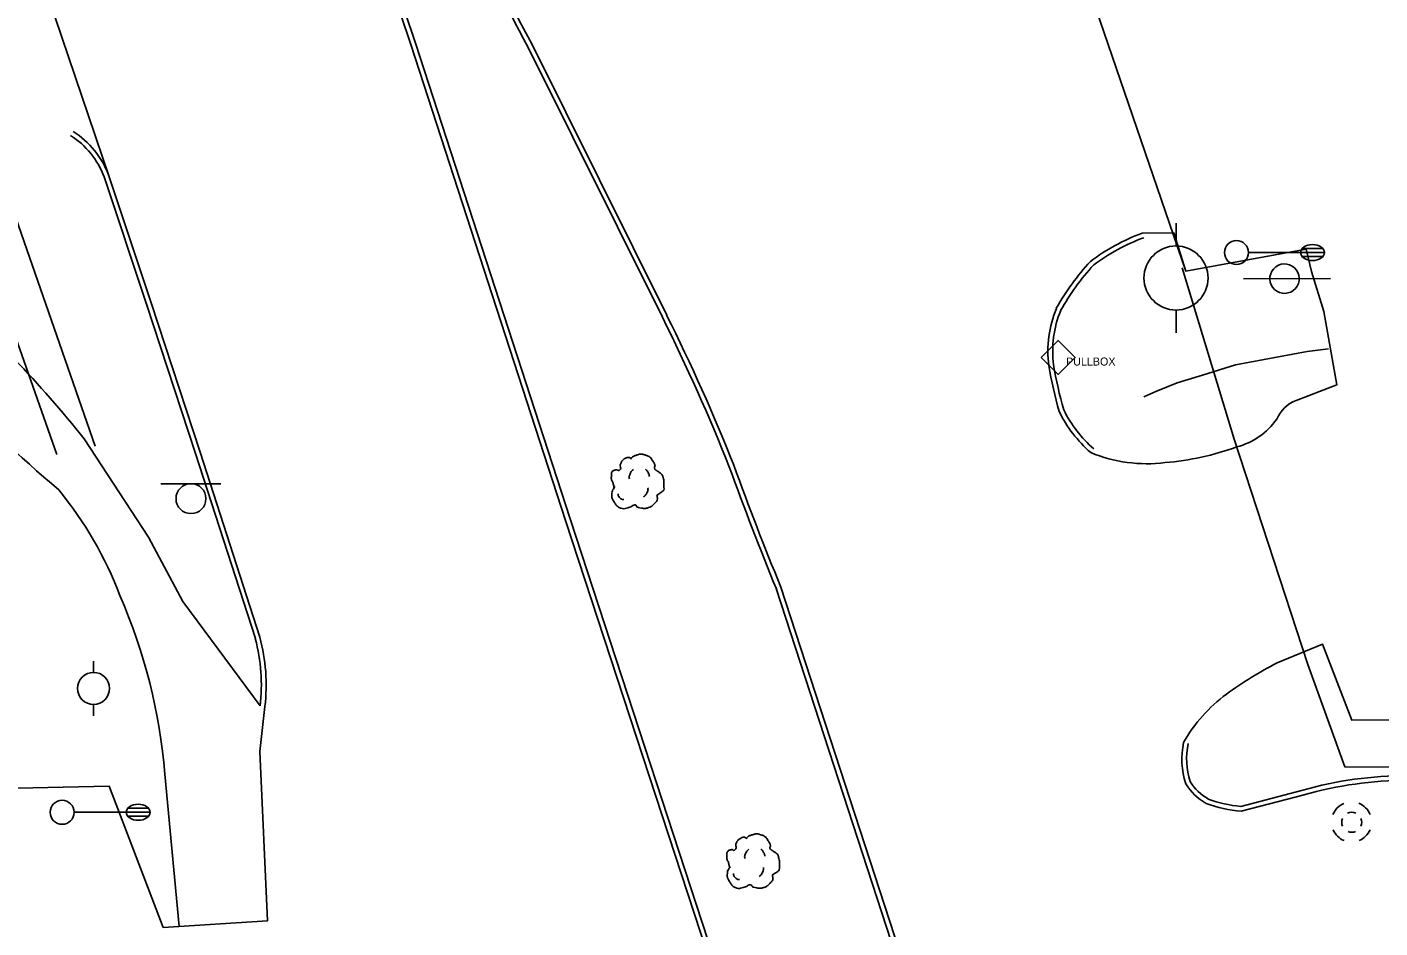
# Model space of a CAD drawing. Extents: x 2145380 to 2157287, y 139568 to 149130.
# Drawn here: x 2147392.4 to 2147561.3, y 142646.5 to 142759 of the extents above; entities that cross this region are included whole.
import ezdxf

# ---------------------------------------------------------------- set-up
doc = ezdxf.new("R2010")
doc.units = 0
for name, color, linetype in [('Default', 7, 'Continuous'), ('TOPO_Asphalt', 7, 'Continuous'), ('TOPO_Concrete', 7, 'Continuous'), ('TOPO_Curb Back', 7, 'Continuous'), ('TOPO_Dirt Grav', 7, 'Continuous'), ('TOPO_DRAIN_Manhole', 7, 'Continuous'), ('TOPO_Fence', 7, 'Continuous'), ('TOPO_Flowline', 7, 'Continuous'), ('TOPO_Guardrail', 7, 'Continuous'), ('TOPO_Light Pole', 7, 'Continuous'), ('TOPO_Power Pole', 7, 'Continuous'), ('TOPO_Power Pullbox', 7, 'Continuous'), ('TOPO_Sign', 7, 'Continuous'), ('TOPO_Tree', 7, 'Continuous')]:
    doc.layers.add(name, color=color, linetype=linetype)

# ---------------------------------------------------------------- blocks, each defined once
blk = doc.blocks.new('POWPOL')
at = {"layer": 'TOPO_Power Pole'}
for p, q in [((0, 10.16), (0, 17.34)), ((0, -10.16), (0, -17.34))]:
    blk.add_line(p, q, dxfattribs=at)
blk.add_circle((0, 0), 10.16, dxfattribs=at)
blk = doc.blocks.new('LP')
at = {"layer": 'TOPO_Light Pole'}
blk.add_line((3.81, 0), (20.32, 0), dxfattribs=at)
for points in [[(20.32, 0), (27.94, 0)], [(20.32, 0), (23.5, 0)], [(20.83, 1.27), (27.43, 1.27)], [(20.83, 1.27), (23.5, 1.27)], [(23.71, 1.27), (27.43, 1.27)], [(23.71, 0), (27.94, 0)], [(20.83, -1.27), (27.43, -1.27)], [(20.83, -1.27), (23.5, -1.27)], [(23.71, -1.27), (27.43, -1.27)]]:
    blk.add_lwpolyline(points, dxfattribs=at)
blk.add_circle((0, 0), 3.81, dxfattribs=at)
blk.add_ellipse((24.13, 0), major_axis=(3.81, 0), ratio=0.666667, dxfattribs=at)
blk = doc.blocks.new('MHEXST')
at = {"layer": 'TOPO_DRAIN_Manhole'}
for centre, radius, start, end in [((-0.14, 0.26), 12.7, 112.97475, 158.26364), ((-0.14, 0.26), 12.7, 22.07441, 68.69913), ((-0.08, 0.11), 6.35, 157.97219, 204.16105), ((-0.08, 0.11), 6.35, 66.19406, 113.69103), ((-0.08, 0.11), 6.35, 336.80229, 21.40458), ((-0.14, 0.26), 12.7, 202.6921, 248.19382), ((-0.08, 0.11), 6.35, 248.57914, 293.19947), ((-0.14, 0.26), 12.7, 291.79631, 337.30323)]:
    blk.add_arc(centre, radius, start, end, dxfattribs=at)
blk = doc.blocks.new('TREE')
at = {"layer": 'TOPO_Tree'}
for points in [[(-14.07, -0.4), (-14.17, 0.5), (-14.37, 1.38), (-14.6, 2.25), (-14.84, 3.17), (-15.47, 3.96), (-15.66, 4.9), (-15.8, 5.59), (-15.71, 6.31), (-15.66, 7.01), (-15.6, 7.91), (-15.72, 8.8), (-15.13, 9.66), (-14.62, 10.42), (-13.76, 10.49), (-13.02, 10.72), (-12.18, 10.98), (-11.06, 10), (-10.37, 10.72), (-9.4, 11.74), (-10.29, 13.28), (-9.84, 14.42), (-9.56, 15.15), (-9.32, 15.89), (-8.78, 16.54), (-8.18, 17.26), (-7.5, 17.68), (-6.67, 18.13), (-6.14, 18.41), (-5.61, 18.61), (-5.08, 18.66), (-4.55, 18.71), (-4.02, 18.54), (-3.49, 18.13)], [(-3.49, 17.6), (-3.07, 18.27), (-2.58, 18.8), (-1.9, 19.19), (-1.05, 19.68), (-0.19, 19.96), (0.74, 20.24), (1.62, 20.51), (2.51, 20.82), (3.39, 20.77), (4.1, 20.73), (4.8, 20.47), (5.51, 20.24), (6.43, 19.95), (7.32, 19.73), (8.15, 19.19), (9.36, 18.4), (10.02, 17.21), (10.8, 16.01), (11.24, 15.33), (11.58, 14.62), (11.86, 13.89), (12.17, 13.08), (11.37, 12.02), (11.86, 11.25), (12, 11.03), (12.18, 10.86), (12.39, 10.72), (12.91, 10.35), (13.45, 10.02), (13.97, 9.66), (14.7, 9.16), (15.41, 8.68), (16.09, 8.07), (16.7, 7.53), (16.93, 6.73), (17.15, 5.95), (17.59, 4.38), (17.71, 2.77), (17.68, 1.19), (17.65, -0.25), (17.83, -2.22), (16.62, -3.04), (15.47, -3.83), (14.31, -4.58), (13.16, -5.35)], [(-4.21, 5.09), (-4.46, 6.09), (-4.3, 7.21), (-3.84, 8.21), (-3.33, 9.34), (-2.71, 10.27), (-1.64, 10.97)], [(5.89, 11.15), (6.5, 10.68), (6.96, 10.17), (7.36, 9.5), (7.93, 8.56), (8.31, 7.6), (8.46, 6.56)], [(13.16, -5.34), (13.25, -5.81), (13.36, -6.28), (13.45, -6.75), (13.76, -8.52), (12.24, -10.03), (10.8, -11.51), (9.98, -12.34), (9.13, -12.77), (8.15, -13.1), (5.97, -13.83), (3.32, -13.56), (1.27, -13.1), (0.49, -12.92), (-0.06, -11.44), (-0.84, -11.51), (-2.04, -11.61), (-3.28, -12.78), (-4.55, -13.1), (-6.06, -13.47), (-7.77, -14.03), (-9.31, -13.62), (-11.36, -13.09), (-12.84, -11.41), (-14.07, -9.39), (-15.32, -7.35), (-15.61, -5.13), (-15.13, -3.04), (-14.87, -1.89), (-13.91, -0.75), (-13.54, 0.13)], [(-11.38, -4.46), (-11.47, -5.41), (-11.03, -6.32), (-10.09, -7.22), (-9.3, -7.97), (-8.49, -8.26), (-7.7, -8.14)], [(4.79, -6.29), (5.71, -5.66), (6.3, -4.92), (6.81, -3.91), (7.36, -2.81), (7.63, -1.7), (7.54, -0.6)]]:
    blk.add_open_spline(points, degree=3, dxfattribs=at)
blk = doc.blocks.new('pulbox')
at = {"layer": 'Default'}
blk.add_lwpolyline([(-5.38, -0.01), (-0.02, 5.42), (5.4, 0.06), (0.05, -5.36), (-5.38, -0.01)], dxfattribs=at)
blk.add_text('PULLBOX', height=2.54, dxfattribs=at).set_placement((2.54, -2.54))

msp = doc.modelspace()

# ---------------------------------------------------------------- linework, layer by layer
at = {"layer": 'TOPO_Asphalt'}
msp.add_line((2147379.12, 142809.78), (2147402.56, 142740.4), dxfattribs=at)
for points in [[(2147550.86, 142712.35), (2147555.96, 142714.29), (2147554.33, 142723.44), (2147552.81, 142728.43), (2147552.15, 142731.25), (2147537.08, 142728.5), (2147535.58, 142733.28), (2147531.64, 142733.22)], [(2147422.07, 142674.13), (2147421.42, 142668.5), (2147422.4, 142647.38), (2147409.37, 142646.54), (2147402.62, 142664.18), (2147370.09, 142663.49), (2147370.88, 142674.99), (2147369.88, 142689.4), (2147296.13, 142688.43), (2147231.46, 142686.35), (2147183.48, 142688.76)], [(2147548.5, 142679.57), (2147554.17, 142681.92), (2147557.82, 142672.43), (2147585.42, 142672.53), (2147630.17, 142671.16), (2147682.2, 142673.05)]]:
    msp.add_lwpolyline(points, dxfattribs=at)
for centre, radius, start, end in [((2147552.55, 142708.21), 4.47, 112.1319, 156.143), ((2147541.31, 142714.98), 8.7, 284.2966, 325.2617), ((2147532.24, 142722.89), 18.45, 247.616, 277.0787), ((2147531.61, 142739.21), 34.75, 274.7926, 289.9424), ((2147571.02, 142635.94), 49.1, 117.298, 125.9626), ((2147553.77, 142659.98), 19.51, 126.4214, 150.3788)]:
    msp.add_arc(centre, radius, start, end, dxfattribs=at)
at = {"layer": 'TOPO_Concrete'}
for points in [[(2147396.06, 142705.59), (2147381.39, 142747.31), (2147377.04, 142753.94)], [(2147385.61, 142754.15), (2147386.11, 142748.91), (2147400.87, 142706.65)]]:
    msp.add_lwpolyline(points, dxfattribs=at)
at = {"layer": 'TOPO_Curb Back'}
for points in [[(2147459.61, 142697.37), (2147440.29, 142756.78), (2147423.84, 142805.62), (2147404.95, 142862.58), (2147403, 142867.87), (2147393.71, 142894.97)], [(2147460.18, 142697.55), (2147440.86, 142756.97), (2147424.41, 142805.81), (2147405.51, 142862.78), (2147403.56, 142868.07), (2147394.27, 142895.2)], [(2147454.92, 142756.5), (2147471.72, 142722.73)], [(2147455.45, 142756.78), (2147472.25, 142723)], [(2147407.84, 142724.54), (2147402.56, 142740.4)], [(2147407.26, 142724.37), (2147401.98, 142740.25)], [(2147420.87, 142682.6), (2147413.39, 142705.72), (2147407.26, 142724.37)], [(2147421.44, 142682.77), (2147413.96, 142705.9), (2147407.84, 142724.54)], [(2147497.63, 142580.22), (2147479.71, 142636.01), (2147459.61, 142697.37)], [(2147498.21, 142580.4), (2147480.28, 142636.2), (2147460.18, 142697.55)], [(2147485.93, 142688.87), (2147505.7, 142628.2), (2147529.94, 142555.48), (2147551.02, 142491.19), (2147560.55, 142462.86)], [(2147486.51, 142689.04), (2147506.27, 142628.39), (2147530.51, 142555.67), (2147551.59, 142491.38), (2147561.18, 142462.86)], [(2147543.97, 142661.66), (2147551.7, 142663.68)], [(2147544.02, 142661.06), (2147551.86, 142663.1)]]:
    msp.add_lwpolyline(points, dxfattribs=at)
for centre, radius, start, end in [((2147535.4, 142801.47), 92.2, 197.8061, 209.1932), ((2147535.4, 142801.47), 91.6, 197.8023, 209.2021), ((2147392.21, 142736.62), 11.02, 20.1005, 57.6944), ((2147392.21, 142736.62), 10.42, 20.3848, 57.6944), ((2147540.39, 142709.46), 25.32, 110.2019, 126.9019), ((2147540.39, 142709.46), 24.72, 110.2019, 126.773), ((2147548.97, 142707.92), 32.26, 137.5085, 150.4182), ((2147548.97, 142707.92), 31.66, 137.6095, 150.3459), ((2147534.31, 142718.43), 14.44, 157.9892, 186.9382), ((2147534.31, 142718.43), 13.84, 158.1526, 186.8742), ((2147263.53, 142618.49), 232.82, 21.5593, 26.5986), ((2147263.53, 142618.49), 233.42, 21.5573, 26.5984), ((2147576.79, 142726.62), 57.08, 189.931, 195.7037), ((2147576.79, 142726.62), 57.68, 189.9152, 195.7601), ((2147536.25, 142718.38), 16.71, 206.3886, 228.6529), ((2147536.25, 142718.38), 16.11, 206.5858, 228.6529), ((2147871.1, 142846.48), 416.17, 200.0144, 202.2631), ((2147871.1, 142846.48), 415.57, 200.0133, 202.2631), ((2147399.04, 142676.81), 22.58, 353.3648, 14.8706), ((2147399.04, 142676.81), 23.18, 353.3648, 14.9105), ((2147546.48, 142667.56), 9.88, 167.8776, 198.0821), ((2147546.48, 142667.56), 9.28, 167.8776, 197.6506), ((2147543.01, 142668.09), 6.93, 211.2729, 240.8411), ((2147543.01, 142668.09), 6.33, 211.897, 240.4314), ((2147564.78, 142617.38), 48.12, 90.0244, 105.7729), ((2147564.78, 142617.38), 47.52, 90.0216, 105.78), ((2147545.35, 142677.41), 16.41, 249.582, 265.3466), ((2147545.35, 142677.41), 15.81, 249.7505, 264.9803)]:
    msp.add_arc(centre, radius, start, end, dxfattribs=at)
at = {"layer": 'TOPO_Dirt Grav'}
for points in [[(2147421.47, 142674.2), (2147411.83, 142687.25), (2147407.52, 142695.26), (2147399.49, 142707.54)], [(2147409.58, 142665.69), (2147411.35, 142646.67)]]:
    msp.add_lwpolyline(points, dxfattribs=at)
for centre, radius, start, end in [((2147291.11, 142621.39), 138.45, 38.4822, 49.4104), ((2147488, 142810.42), 142.62, 222.1637, 229.9976), ((2147360, 142671.36), 46.98, 20.7329, 39.374), ((2147338.99, 142659.71), 70.84, 4.8444, 23.5278)]:
    msp.add_arc(centre, radius, start, end, dxfattribs=at)
at = {"layer": 'TOPO_Fence'}
for p, q in [((2147537.08, 142728.5), (2147523.83, 142767.24)), ((2147552.34, 142679.39), (2147543.14, 142707.52))]:
    msp.add_line(p, q, dxfattribs=at)
msp.add_lwpolyline([(2147613.89, 142644.09), (2147613.51, 142666.68), (2147556.97, 142666.57)], dxfattribs=at)
at = {"layer": 'TOPO_Flowline'}
msp.add_lwpolyline([(2147554.92, 142718.8), (2147552.27, 142718.46), (2147543.32, 142716.79), (2147539.2, 142715.51), (2147536.02, 142714.55), (2147533.34, 142713.45), (2147531.87, 142712.81)], dxfattribs=at)
at = {"layer": 'TOPO_Guardrail'}
for p, q in [((2147543.14, 142707.52), (2147536.66, 142728.88)), ((2147556.94, 142666.59), (2147552.34, 142679.39))]:
    msp.add_line(p, q, dxfattribs=at)
at = {"layer": 'TOPO_Sign'}
for points in [[(2147544.29, 142727.52), (2147555.17, 142727.58)], [(2147409.08, 142701.95), (2147416.57, 142701.95)], [(2147412.83, 142701.95), (2147412.83, 142701.95)], [(2147410.96, 142700.08), (2147410.96, 142700.08)], [(2147414.7, 142700.08), (2147414.7, 142700.08)], [(2147412.83, 142698.21), (2147412.83, 142698.21)]]:
    msp.add_lwpolyline(points, dxfattribs=at)
for centre, radius, start, end in [((2147549.43, 142727.55), 1.84, 47.4196, 227.4196), ((2147549.43, 142727.55), 1.84, 227.4196, 47.4196), ((2147412.83, 142700.08), 1.87, 90, 180), ((2147412.83, 142700.08), 1.87, 360, 90), ((2147412.83, 142700.08), 1.87, 180, 270), ((2147412.83, 142700.08), 1.87, 270, 0)]:
    msp.add_arc(centre, radius, start, end, dxfattribs=at)

# ---------------------------------------------------------------- block references
at = {"layer": 'TOPO_DRAIN_Manhole', "xscale": 0.19685000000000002, "yscale": 0.19685000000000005}
msp.add_blockref('MHEXST', (2147557.83, 142659.66), dxfattribs=at)
at = {"layer": 'TOPO_Light Pole', "xscale": 0.39370000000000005, "yscale": 0.3937000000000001}
for p in [(2147543.42, 142730.81), (2147396.73, 142660.92)]:
    msp.add_blockref('LP', p, dxfattribs=at)
at = {"layer": 'TOPO_Power Pole'}
for p, xscale, yscale in [((2147535.87, 142727.63), 0.39370000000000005, 0.3937000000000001), ((2147400.66, 142676.39), 0.19685000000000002, 0.19685000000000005)]:
    msp.add_blockref('POWPOL', p, dxfattribs=dict(at, xscale=xscale, yscale=yscale))
at = {"layer": 'TOPO_Power Pullbox', "xscale": 0.39370000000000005, "yscale": 0.3937000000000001}
msp.add_blockref('pulbox', (2147521.14, 142717.7), dxfattribs=at)
at = {"layer": 'TOPO_Tree', "xscale": 0.19685000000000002, "yscale": 0.19685000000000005}
for p in [(2147468.43, 142701.56), (2147482.85, 142654.14)]:
    msp.add_blockref('TREE', p, dxfattribs=at)

doc.saveas('drawing.dxf')
